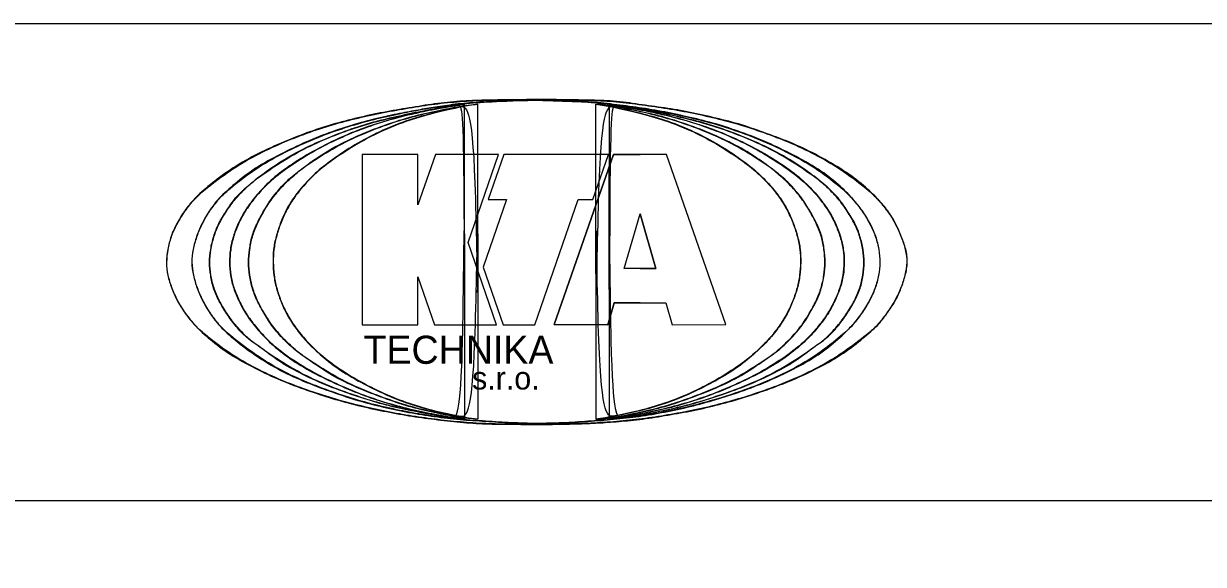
# Model space of a CAD drawing. Extents: x -729968 to -728918, y -1073811 to -1072326.
# Drawn here: x -729327.8 to -729080.2, y -1073214.6 to -1073101.1 of the extents above; entities that cross this region are included whole.
import ezdxf

# ---------------------------------------------------------------- set-up
doc = ezdxf.new("R2010")
doc.units = 0
doc.layers.add('_popis', color=7, linetype='Continuous')
doc.layers.add('Rozpiska_pole_6', color=7, linetype='Continuous')

msp = doc.modelspace()

# ---------------------------------------------------------------- linework, layer by layer
at = {"layer": '_popis'}
for p, q in [((-729198.42, -1073141.01), (-729195.1, -1073152.49)), ((-729195.1, -1073152.49), (-729198.42, -1073152.49))]:
    msp.add_line(p, q, dxfattribs=at)
for points in [[(-729256.7, -1073128.58), (-729256.7, -1073164.29), (-729245.02, -1073164.29), (-729245.02, -1073154.22), (-729241.52, -1073164.29), (-729228.52, -1073164.29), (-729234.52, -1073147.06), (-729228.09, -1073128.58), (-729241.34, -1073128.58), (-729245.02, -1073139.17), (-729245.02, -1073128.58), (-729256.7, -1073128.58)], [(-729256.7, -1073128.58), (-729256.7, -1073164.29), (-729245.02, -1073164.29), (-729245.02, -1073154.22), (-729241.52, -1073164.29), (-729228.52, -1073164.29), (-729234.52, -1073147.06), (-729228.09, -1073128.58), (-729241.34, -1073128.58), (-729245.02, -1073139.17), (-729245.02, -1073128.58), (-729256.7, -1073128.58)], [(-729227.02, -1073128.58), (-729230.3, -1073138.02), (-729226.42, -1073138.02), (-729231.36, -1073152.21), (-729227.16, -1073164.29), (-729220.51, -1073164.29), (-729211.37, -1073138.02), (-729208.35, -1073138.02), (-729205.06, -1073128.58), (-729227.02, -1073128.58)], [(-729227.02, -1073128.58), (-729230.3, -1073138.02), (-729226.42, -1073138.02), (-729231.36, -1073152.21), (-729227.16, -1073164.29), (-729220.51, -1073164.29), (-729211.37, -1073138.02), (-729208.35, -1073138.02), (-729205.06, -1073128.58), (-729227.02, -1073128.58)], [(-729198.42, -1073159.72), (-729203.83, -1073159.72), (-729205.15, -1073164.29), (-729216.42, -1073164.28), (-729203.99, -1073128.58), (-729198.42, -1073128.58)], [(-729198.42, -1073128.58), (-729203.99, -1073128.58), (-729216.42, -1073164.28), (-729205.15, -1073164.29), (-729203.83, -1073159.72), (-729198.42, -1073159.72)], [(-729198.42, -1073159.72), (-729193.01, -1073159.72), (-729191.69, -1073164.29), (-729180.43, -1073164.28), (-729192.85, -1073128.58), (-729198.42, -1073128.58)], [(-729198.42, -1073159.72), (-729193.01, -1073159.72), (-729191.69, -1073164.29), (-729180.43, -1073164.28), (-729192.85, -1073128.58), (-729198.42, -1073128.58)], [(-729198.42, -1073152.49), (-729201.74, -1073152.49), (-729198.42, -1073141.01)], [(-729198.42, -1073152.49), (-729201.74, -1073152.49), (-729198.42, -1073141.01)], [(-729198.42, -1073152.49), (-729195.1, -1073152.49), (-729198.42, -1073141.01)]]:
    msp.add_lwpolyline(points, dxfattribs=at)
for points in [[(-729220.07, -1073117.05), (-729222.09, -1073117.09), (-729225.67, -1073117.14), (-729231.03, -1073117.18), (-729236.17, -1073117.36), (-729241.53, -1073117.93), (-729246.88, -1073118.83), (-729252.26, -1073119.71), (-729257.63, -1073120.87), (-729263.01, -1073122.26), (-729268.39, -1073124.01), (-729273.74, -1073126.17), (-729279.19, -1073128.61), (-729284.59, -1073131.83), (-729288.82, -1073134.98), (-729292.04, -1073137.91), (-729294.02, -1073140.37), (-729295.67, -1073143.1), (-729296.94, -1073145.77), (-729297.53, -1073148.51), (-729297.93, -1073151.2), (-729297.6, -1073153.94), (-729296.75, -1073156.62), (-729295.56, -1073159.36), (-729293.8, -1073162.03), (-729291.93, -1073164.48), (-729288.75, -1073167.34), (-729284.65, -1073170.51), (-729279.15, -1073173.5), (-729273.79, -1073176.04), (-729268.37, -1073178.03), (-729263, -1073179.79), (-729257.64, -1073181.26), (-729252.28, -1073182.42), (-729246.92, -1073183.41), (-729241.53, -1073184.16), (-729236.17, -1073184.75), (-729230.8, -1073185.17), (-729225.44, -1073185.11), (-729220.07, -1073185.3), (-729214.71, -1073185.13), (-729210.61, -1073185.08), (-729208.3, -1073184.96), (-729207.78, -1073184.93)], [(-729220.07, -1073117.05), (-729226.13, -1073117.14), (-729230.79, -1073117.2), (-729236.15, -1073117.42), (-729241.51, -1073117.98), (-729246.87, -1073118.82), (-729252.24, -1073119.75), (-729257.6, -1073120.9), (-729262.96, -1073122.31), (-729268.33, -1073124.06), (-729273.69, -1073126.19), (-729279.02, -1073128.66), (-729284.39, -1073131.83), (-729289.75, -1073135.87), (-729291.84, -1073137.82), (-729294.02, -1073140.51), (-729295.65, -1073143.17), (-729296.86, -1073145.86), (-729297.5, -1073148.53), (-729297.81, -1073151.22), (-729297.53, -1073153.86), (-729296.72, -1073156.57), (-729295.51, -1073159.26), (-729293.83, -1073161.92), (-729291.67, -1073164.62), (-729289.76, -1073166.4), (-729284.4, -1073170.47), (-729279.04, -1073173.5), (-729273.74, -1073175.97), (-729268.32, -1073178.01), (-729262.94, -1073179.76), (-729257.61, -1073181.22), (-729252.28, -1073182.39), (-729246.89, -1073183.38), (-729241.52, -1073184.14), (-729236.13, -1073184.73), (-729230.83, -1073185.09), (-729225.43, -1073185.15), (-729220.07, -1073185.24), (-729214.71, -1073185.15), (-729209.34, -1073185.01), (-729203.98, -1073184.67), (-729198.65, -1073184.17), (-729193.27, -1073183.35), (-729187.91, -1073182.4), (-729182.55, -1073181.2), (-729177.18, -1073179.71), (-729171.82, -1073177.94), (-729166.46, -1073175.87), (-729161.13, -1073173.37), (-729155.73, -1073170.21), (-729150.34, -1073166.03), (-729148.74, -1073164.6), (-729146.64, -1073161.94), (-729144.87, -1073159.28), (-729143.63, -1073156.57), (-729142.76, -1073153.91), (-729142.33, -1073151.22), (-729142.65, -1073148.55), (-729143.57, -1073145.85), (-729144.78, -1073143.12), (-729146.38, -1073140.51), (-729148.65, -1073137.82), (-729150.3, -1073136.19), (-729155.72, -1073132), (-729161.08, -1073128.83), (-729166.4, -1073126.29), (-729171.79, -1073124.22), (-729177.18, -1073122.37), (-729182.51, -1073120.96), (-729187.91, -1073119.76), (-729193.3, -1073118.83), (-729198.68, -1073118.07), (-729204, -1073117.4), (-729209.35, -1073117.2), (-729214.7, -1073117.11), (-729220.07, -1073117.05), (-729220.07, -1073117.05), (-729220.07, -1073117.05)], [(-729207.78, -1073184.93), (-729206.52, -1073184.86), (-729203.47, -1073184.64), (-729198.61, -1073184.24), (-729193.27, -1073183.36), (-729187.89, -1073182.45), (-729182.52, -1073181.23), (-729177.14, -1073179.75), (-729171.77, -1073177.97), (-729166.39, -1073175.91), (-729160.98, -1073173.39), (-729155.47, -1073170.26), (-729151.54, -1073167.04), (-729148.37, -1073164.39), (-729146.68, -1073161.99), (-729144.81, -1073159.4), (-729143.61, -1073156.64), (-729142.7, -1073153.95), (-729142.19, -1073151.24), (-729142.55, -1073148.46), (-729143.58, -1073145.8), (-729144.72, -1073143.06), (-729146.4, -1073140.33), (-729148.35, -1073138.08), (-729151.36, -1073135.11), (-729155.48, -1073132), (-729160.95, -1073128.81), (-729166.33, -1073126.22), (-729171.76, -1073124.22), (-729177.09, -1073122.29), (-729182.51, -1073120.95), (-729187.88, -1073119.7), (-729193.29, -1073118.8), (-729198.66, -1073118.1), (-729203.99, -1073117.27), (-729209.35, -1073117.21), (-729214.71, -1073117.09), (-729218.28, -1073117.07), (-729220.07, -1073117.05)], [(-729220.07, -1073117.2), (-729218.28, -1073117.27), (-729214.7, -1073117.42), (-729209.33, -1073117.47), (-729203.98, -1073118.06), (-729198.62, -1073118.74), (-729193.24, -1073119.63), (-729187.89, -1073120.82), (-729182.48, -1073122.1), (-729177.13, -1073123.92), (-729171.72, -1073125.99), (-729166.38, -1073128.63), (-729160.8, -1073131.63), (-729156.69, -1073134.91), (-729153.64, -1073137.96), (-729151.72, -1073140.39), (-729150.07, -1073143.1), (-729148.84, -1073145.79), (-729148.2, -1073148.52), (-729147.97, -1073151.23), (-729148.17, -1073153.96), (-729148.99, -1073156.65), (-729150.19, -1073159.35), (-729151.9, -1073162.03), (-729153.72, -1073164.42), (-729156.81, -1073167.32), (-729160.8, -1073170.61), (-729166.34, -1073173.73), (-729171.75, -1073176.24), (-729177.13, -1073178.32), (-729182.52, -1073180.01), (-729187.88, -1073181.51), (-729193.26, -1073182.62), (-729198.62, -1073183.6), (-729203.99, -1073184.13), (-729209.35, -1073184.58), (-729214.7, -1073184.93), (-729220.07, -1073185.1), (-729225.44, -1073184.9), (-729230.8, -1073184.52), (-729236.17, -1073184.23), (-729241.54, -1073183.59), (-729246.91, -1073182.72), (-729252.27, -1073181.58), (-729257.67, -1073180.25), (-729263, -1073178.41), (-729268.42, -1073176.47), (-729273.85, -1073174), (-729279.24, -1073170.74), (-729283.47, -1073167.52), (-729286.7, -1073164.57), (-729288.63, -1073162.06), (-729290.23, -1073159.33), (-729291.43, -1073156.64), (-729292.18, -1073153.94), (-729292.65, -1073151.22), (-729292.24, -1073148.5), (-729291.54, -1073145.79), (-729290.41, -1073143.09), (-729288.82, -1073140.39), (-729286.89, -1073137.76), (-729283.54, -1073134.78), (-729279.31, -1073131.41), (-729273.76, -1073128.45), (-729268.42, -1073125.86), (-729263.03, -1073123.76), (-729257.65, -1073122.04), (-729252.27, -1073120.67), (-729247.69, -1073119.76), (-729244.11, -1073119.1), (-729240.54, -1073118.53), (-729236.17, -1073117.89), (-729230.8, -1073117.55), (-729225.43, -1073117.33), (-729221.86, -1073117.24), (-729220.07, -1073117.2)], [(-729220.07, -1073117.2), (-729225.43, -1073117.34), (-729230.79, -1073117.57), (-729236.15, -1073117.96), (-729241.51, -1073118.69), (-729243.92, -1073119.08), (-729246.87, -1073119.61), (-729252.24, -1073120.71), (-729257.6, -1073122.09), (-729262.97, -1073123.8), (-729268.33, -1073125.91), (-729273.7, -1073128.46), (-729279.03, -1073131.46), (-729284.39, -1073135.56), (-729286.78, -1073137.81), (-729288.83, -1073140.5), (-729290.37, -1073143.17), (-729291.49, -1073145.87), (-729292.2, -1073148.53), (-729292.5, -1073151.22), (-729292.14, -1073153.9), (-729291.38, -1073156.56), (-729290.2, -1073159.25), (-729288.63, -1073161.94), (-729286.52, -1073164.63), (-729284.39, -1073166.65), (-729279.03, -1073170.74), (-729273.7, -1073173.95), (-729268.34, -1073176.41), (-729262.98, -1073178.41), (-729257.61, -1073180.18), (-729252.25, -1073181.56), (-729246.89, -1073182.68), (-729241.52, -1073183.55), (-729236.16, -1073184.17), (-729230.8, -1073184.53), (-729225.43, -1073184.87), (-729220.07, -1073185.04), (-729214.71, -1073184.9), (-729209.34, -1073184.56), (-729204.01, -1073184.12), (-729198.65, -1073183.53), (-729193.27, -1073182.6), (-729187.92, -1073181.45), (-729182.56, -1073179.99), (-729177.18, -1073178.28), (-729171.82, -1073176.2), (-729166.46, -1073173.71), (-729161.09, -1073170.57), (-729155.73, -1073166.29), (-729154.02, -1073164.62), (-729151.89, -1073161.93), (-729150.23, -1073159.26), (-729149.02, -1073156.57), (-729148.27, -1073153.91), (-729148.04, -1073151.24), (-729148.27, -1073148.54), (-729148.91, -1073145.88), (-729150.09, -1073143.19), (-729151.72, -1073140.5), (-729153.85, -1073137.81), (-729155.73, -1073135.91), (-729161.09, -1073131.67), (-729166.46, -1073128.63), (-729171.82, -1073126.05), (-729177.18, -1073123.95), (-729182.55, -1073122.17), (-729187.9, -1073120.83), (-729193.26, -1073119.68), (-729198.64, -1073118.77), (-729203.99, -1073118.07), (-729209.34, -1073117.56), (-729214.7, -1073117.39), (-729220.07, -1073117.2), (-729220.07, -1073117.2), (-729220.07, -1073117.2)], [(-729235.26, -1073184.04), (-729236.28, -1073183.96), (-729238.39, -1073183.79), (-729242.28, -1073183.19), (-729246.92, -1073182.23), (-729252.35, -1073181.08), (-729257.69, -1073179.37), (-729263.08, -1073177.51), (-729268.47, -1073175.18), (-729273.95, -1073172.24), (-729277.75, -1073169.24), (-729281.14, -1073167.01), (-729283.15, -1073164.75), (-729285.19, -1073162.02), (-729286.78, -1073159.33), (-729288.02, -1073156.67), (-729288.56, -1073153.92), (-729288.86, -1073151.22), (-729288.57, -1073148.51), (-729287.95, -1073145.8), (-729286.91, -1073143.04), (-729285.24, -1073140.43), (-729283.33, -1073137.59), (-729281.13, -1073135.48), (-729277.93, -1073132.87), (-729273.9, -1073130.04), (-729268.46, -1073126.98), (-729263.03, -1073124.71), (-729257.69, -1073122.67), (-729252.28, -1073121.22), (-729246.87, -1073120), (-729241.52, -1073118.94), (-729237.65, -1073118.25), (-729235.56, -1073118.12), (-729235.28, -1073118.1)], [(-729235.26, -1073184.04), (-729238.33, -1073183.75), (-729241.54, -1073183.28), (-729246.9, -1073182.23), (-729252.29, -1073181), (-729257.67, -1073179.35), (-729263, -1073177.46), (-729268.34, -1073175.15), (-729273.72, -1073172.17), (-729279.11, -1073168.36), (-729280.55, -1073167.33), (-729283.18, -1073164.63), (-729285.21, -1073161.88), (-729286.76, -1073159.26), (-729287.92, -1073156.6), (-729288.53, -1073153.88), (-729288.77, -1073151.2), (-729288.53, -1073148.58), (-729287.9, -1073145.85), (-729286.85, -1073143.15), (-729285.27, -1073140.49), (-729283.35, -1073137.81), (-729280.62, -1073135.08), (-729279.14, -1073133.87), (-729273.72, -1073130.05), (-729268.3, -1073127.03), (-729262.96, -1073124.71), (-729257.68, -1073122.77), (-729252.19, -1073121.24), (-729246.88, -1073120.03), (-729241.49, -1073118.95), (-729236.12, -1073118.16), (-729235.28, -1073118.1), (-729235.26, -1073184.04), (-729235.28, -1073118.1)], [(-729235.28, -1073118.1), (-729237.21, -1073118.39), (-729241.1, -1073118.98), (-729246.77, -1073120.14), (-729252.3, -1073121.67), (-729257.71, -1073123.45), (-729263.06, -1073125.82), (-729268.47, -1073128.65), (-729273.21, -1073131.75), (-729276.94, -1073134.86), (-729279.41, -1073137.71), (-729281.36, -1073140.38), (-729282.8, -1073143.08), (-729283.84, -1073145.8), (-729284.46, -1073148.52), (-729284.64, -1073151.23), (-729284.44, -1073153.94), (-729283.76, -1073156.65), (-729282.61, -1073159.31), (-729281.2, -1073162.07), (-729279.18, -1073164.71), (-729276.73, -1073167.5), (-729273.14, -1073170.6), (-729268.47, -1073173.64), (-729263.04, -1073176.37), (-729257.65, -1073178.66), (-729252.3, -1073180.58), (-729246.91, -1073182.01), (-729242.05, -1073183), (-729238.17, -1073183.65), (-729236.07, -1073183.93), (-729235.26, -1073184.04)], [(-729235.28, -1073118.1), (-729241.06, -1073119.02), (-729246.87, -1073120.23), (-729252.26, -1073121.7), (-729257.64, -1073123.53), (-729262.95, -1073125.84), (-729268.31, -1073128.67), (-729273.69, -1073132.24), (-729277.05, -1073135.13), (-729279.45, -1073137.83), (-729281.34, -1073140.49), (-729282.76, -1073143.14), (-729283.79, -1073145.86), (-729284.39, -1073148.56), (-729284.58, -1073151.22), (-729284.37, -1073153.92), (-729283.71, -1073156.57), (-729282.6, -1073159.25), (-729281.16, -1073161.96), (-729279.21, -1073164.61), (-729276.82, -1073167.28), (-729273.64, -1073170.07), (-729268.33, -1073173.59), (-729262.94, -1073176.35), (-729257.59, -1073178.63), (-729252.23, -1073180.52), (-729246.89, -1073181.96), (-729241.51, -1073183.07), (-729237.7, -1073183.7), (-729235.26, -1073184.04), (-729235.28, -1073118.1), (-729235.26, -1073184.04)], [(-729232.46, -1073184.13), (-729233.7, -1073184.02), (-729236.75, -1073183.76), (-729241.53, -1073182.73), (-729246.94, -1073181.52), (-729252.28, -1073179.67), (-729257.69, -1073177.59), (-729263.18, -1073174.99), (-729267.22, -1073172.12), (-729270.8, -1073169.76), (-729273.17, -1073167.41), (-729275.61, -1073164.79), (-729277.26, -1073161.97), (-729278.8, -1073159.35), (-729279.84, -1073156.65), (-729280.41, -1073153.94), (-729280.7, -1073151.23), (-729280.38, -1073148.53), (-729279.96, -1073145.79), (-729278.85, -1073143.11), (-729277.42, -1073140.44), (-729275.68, -1073137.69), (-729273.41, -1073134.94), (-729270.84, -1073132.66), (-729267.35, -1073130.03), (-729263.13, -1073127.27), (-729257.7, -1073124.6), (-729252.31, -1073122.51), (-729246.95, -1073120.74), (-729241.55, -1073119.52), (-729236.74, -1073118.52), (-729233.69, -1073118.17), (-729232.46, -1073118.03)], [(-729232.46, -1073184.13), (-729236.15, -1073183.75), (-729241.54, -1073182.72), (-729246.85, -1073181.44), (-729252.24, -1073179.65), (-729257.61, -1073177.54), (-729262.95, -1073174.91), (-729268.32, -1073171.4), (-729270.34, -1073169.99), (-729273.26, -1073167.28), (-729275.58, -1073164.63), (-729277.29, -1073161.93), (-729278.76, -1073159.25), (-729279.78, -1073156.57), (-729280.36, -1073153.95), (-729280.6, -1073151.23), (-729280.36, -1073148.52), (-729279.86, -1073145.87), (-729278.84, -1073143.21), (-729277.39, -1073140.47), (-729275.68, -1073137.82), (-729273.45, -1073135.13), (-729270.51, -1073132.45), (-729268.3, -1073130.77), (-729262.95, -1073127.31), (-729257.62, -1073124.66), (-729252.23, -1073122.53), (-729246.91, -1073120.82), (-729241.54, -1073119.53), (-729236.15, -1073118.5), (-729232.46, -1073118.03), (-729232.46, -1073184.13), (-729232.46, -1073118.03)], [(-729232.46, -1073118.03), (-729233.69, -1073118.21), (-729236.74, -1073118.65), (-729241.54, -1073119.84), (-729246.97, -1073121.28), (-729252.37, -1073123.39), (-729257.76, -1073126.16), (-729262.49, -1073129.25), (-729266.36, -1073132.23), (-729269.06, -1073135.02), (-729271.19, -1073137.7), (-729272.81, -1073140.41), (-729273.97, -1073143.13), (-729274.84, -1073145.82), (-729275.4, -1073148.51), (-729275.48, -1073151.22), (-729275.32, -1073153.92), (-729274.8, -1073156.63), (-729273.84, -1073159.3), (-729272.66, -1073162.03), (-729270.97, -1073164.7), (-729268.84, -1073167.42), (-729266.14, -1073170.08), (-729262.46, -1073173.14), (-729257.77, -1073176.07), (-729252.35, -1073178.74), (-729246.98, -1073180.94), (-729241.56, -1073182.44), (-729236.72, -1073183.45), (-729233.7, -1073183.93), (-729232.46, -1073184.13)], [(-729232.46, -1073118.03), (-729236.15, -1073118.62), (-729241.5, -1073119.85), (-729246.89, -1073121.37), (-729252.24, -1073123.44), (-729257.61, -1073126.2), (-729262.96, -1073129.68), (-729266.48, -1073132.48), (-729269.09, -1073135.14), (-729271.19, -1073137.83), (-729272.77, -1073140.49), (-729273.94, -1073143.18), (-729274.8, -1073145.86), (-729275.32, -1073148.55), (-729275.44, -1073151.21), (-729275.27, -1073153.9), (-729274.74, -1073156.59), (-729273.83, -1073159.25), (-729272.63, -1073161.93), (-729270.96, -1073164.62), (-729268.88, -1073167.25), (-729266.19, -1073169.95), (-729262.97, -1073172.62), (-729257.62, -1073176.04), (-729252.25, -1073178.71), (-729246.9, -1073180.85), (-729241.49, -1073182.4), (-729236.15, -1073183.51), (-729232.46, -1073184.13), (-729232.46, -1073118.03), (-729232.46, -1073184.13)], [(-729207.68, -1073184.13), (-729206.45, -1073184.02), (-729203.39, -1073183.76), (-729198.61, -1073182.73), (-729193.2, -1073181.52), (-729187.86, -1073179.67), (-729182.45, -1073177.59), (-729176.97, -1073174.99), (-729172.93, -1073172.12), (-729169.34, -1073169.76), (-729166.97, -1073167.41), (-729164.54, -1073164.79), (-729162.88, -1073161.97), (-729161.34, -1073159.35), (-729160.31, -1073156.65), (-729159.74, -1073153.94), (-729159.44, -1073151.23), (-729159.76, -1073148.53), (-729160.19, -1073145.79), (-729161.29, -1073143.11), (-729162.73, -1073140.44), (-729164.47, -1073137.69), (-729166.74, -1073134.94), (-729169.3, -1073132.66), (-729172.79, -1073130.03), (-729177.01, -1073127.27), (-729182.44, -1073124.6), (-729187.83, -1073122.51), (-729193.19, -1073120.74), (-729198.59, -1073119.52), (-729203.4, -1073118.52), (-729206.45, -1073118.17), (-729207.68, -1073118.03)], [(-729207.68, -1073118.03), (-729206.45, -1073118.21), (-729203.4, -1073118.65), (-729198.6, -1073119.84), (-729193.18, -1073121.28), (-729187.77, -1073123.39), (-729182.38, -1073126.16), (-729177.65, -1073129.25), (-729173.79, -1073132.23), (-729171.08, -1073135.02), (-729168.95, -1073137.7), (-729167.34, -1073140.41), (-729166.17, -1073143.13), (-729165.31, -1073145.82), (-729164.74, -1073148.51), (-729164.66, -1073151.22), (-729164.82, -1073153.92), (-729165.34, -1073156.63), (-729166.3, -1073159.3), (-729167.48, -1073162.03), (-729169.17, -1073164.7), (-729171.31, -1073167.42), (-729174.01, -1073170.08), (-729177.69, -1073173.14), (-729182.38, -1073176.07), (-729187.79, -1073178.74), (-729193.17, -1073180.94), (-729198.59, -1073182.44), (-729203.42, -1073183.45), (-729206.45, -1073183.93), (-729207.68, -1073184.13)], [(-729207.68, -1073118.03), (-729203.99, -1073118.62), (-729198.64, -1073119.85), (-729193.26, -1073121.37), (-729187.9, -1073123.44), (-729182.54, -1073126.2), (-729177.18, -1073129.68), (-729173.66, -1073132.48), (-729171.06, -1073135.14), (-729168.95, -1073137.83), (-729167.37, -1073140.49), (-729166.2, -1073143.18), (-729165.35, -1073145.86), (-729164.82, -1073148.55), (-729164.7, -1073151.21), (-729164.88, -1073153.9), (-729165.4, -1073156.59), (-729166.31, -1073159.25), (-729167.51, -1073161.93), (-729169.18, -1073164.62), (-729171.26, -1073167.25), (-729173.96, -1073169.95), (-729177.17, -1073172.62), (-729182.53, -1073176.04), (-729187.89, -1073178.71), (-729193.24, -1073180.85), (-729198.66, -1073182.4), (-729203.99, -1073183.51), (-729207.68, -1073184.13), (-729207.68, -1073118.03), (-729207.68, -1073184.13)], [(-729207.68, -1073184.13), (-729203.99, -1073183.75), (-729198.61, -1073182.72), (-729193.3, -1073181.44), (-729187.91, -1073179.65), (-729182.53, -1073177.54), (-729177.2, -1073174.91), (-729171.82, -1073171.4), (-729169.8, -1073169.99), (-729166.88, -1073167.28), (-729164.57, -1073164.63), (-729162.86, -1073161.93), (-729161.39, -1073159.25), (-729160.36, -1073156.57), (-729159.78, -1073153.95), (-729159.54, -1073151.23), (-729159.78, -1073148.52), (-729160.28, -1073145.87), (-729161.3, -1073143.21), (-729162.75, -1073140.47), (-729164.46, -1073137.82), (-729166.69, -1073135.13), (-729169.64, -1073132.45), (-729171.85, -1073130.77), (-729177.19, -1073127.31), (-729182.52, -1073124.66), (-729187.91, -1073122.53), (-729193.24, -1073120.82), (-729198.6, -1073119.53), (-729204, -1073118.5), (-729207.68, -1073118.03), (-729207.68, -1073184.13), (-729207.68, -1073118.03)], [(-729204.86, -1073118.1), (-729202.93, -1073118.39), (-729199.05, -1073118.98), (-729193.37, -1073120.14), (-729187.84, -1073121.67), (-729182.43, -1073123.45), (-729177.08, -1073125.82), (-729171.67, -1073128.65), (-729166.93, -1073131.75), (-729163.21, -1073134.86), (-729160.73, -1073137.71), (-729158.79, -1073140.38), (-729157.34, -1073143.08), (-729156.3, -1073145.8), (-729155.69, -1073148.52), (-729155.5, -1073151.23), (-729155.7, -1073153.94), (-729156.38, -1073156.65), (-729157.53, -1073159.31), (-729158.94, -1073162.07), (-729160.96, -1073164.71), (-729163.41, -1073167.5), (-729167, -1073170.6), (-729171.67, -1073173.64), (-729177.11, -1073176.37), (-729182.49, -1073178.66), (-729187.84, -1073180.58), (-729193.23, -1073182.01), (-729198.09, -1073183), (-729201.98, -1073183.65), (-729204.07, -1073183.93), (-729204.88, -1073184.04)], [(-729204.88, -1073184.04), (-729203.86, -1073183.96), (-729201.75, -1073183.79), (-729197.87, -1073183.19), (-729193.22, -1073182.23), (-729187.8, -1073181.08), (-729182.46, -1073179.37), (-729177.07, -1073177.51), (-729171.67, -1073175.18), (-729166.2, -1073172.24), (-729162.39, -1073169.24), (-729159, -1073167.01), (-729156.99, -1073164.75), (-729154.95, -1073162.02), (-729153.36, -1073159.33), (-729152.13, -1073156.67), (-729151.58, -1073153.92), (-729151.28, -1073151.22), (-729151.57, -1073148.51), (-729152.19, -1073145.8), (-729153.23, -1073143.04), (-729154.9, -1073140.43), (-729156.82, -1073137.59), (-729159.01, -1073135.48), (-729162.21, -1073132.87), (-729166.25, -1073130.04), (-729171.68, -1073126.98), (-729177.11, -1073124.71), (-729182.46, -1073122.67), (-729187.86, -1073121.22), (-729193.27, -1073120), (-729198.62, -1073118.94), (-729202.5, -1073118.25), (-729204.58, -1073118.12), (-729204.86, -1073118.1)], [(-729204.88, -1073184.04), (-729201.81, -1073183.75), (-729198.6, -1073183.28), (-729193.24, -1073182.23), (-729187.85, -1073181), (-729182.48, -1073179.35), (-729177.14, -1073177.46), (-729171.8, -1073175.15), (-729166.43, -1073172.17), (-729161.04, -1073168.36), (-729159.59, -1073167.33), (-729156.96, -1073164.63), (-729154.93, -1073161.88), (-729153.38, -1073159.26), (-729152.22, -1073156.6), (-729151.61, -1073153.88), (-729151.38, -1073151.2), (-729151.61, -1073148.58), (-729152.24, -1073145.85), (-729153.3, -1073143.15), (-729154.87, -1073140.49), (-729156.79, -1073137.81), (-729159.53, -1073135.08), (-729161, -1073133.87), (-729166.43, -1073130.05), (-729171.84, -1073127.03), (-729177.18, -1073124.71), (-729182.47, -1073122.77), (-729187.95, -1073121.24), (-729193.26, -1073120.03), (-729198.65, -1073118.95), (-729204.02, -1073118.16), (-729204.86, -1073118.1), (-729204.88, -1073184.04), (-729204.86, -1073118.1)], [(-729204.86, -1073118.1), (-729199.08, -1073119.02), (-729193.27, -1073120.23), (-729187.88, -1073121.7), (-729182.5, -1073123.53), (-729177.19, -1073125.84), (-729171.83, -1073128.67), (-729166.45, -1073132.24), (-729163.09, -1073135.13), (-729160.7, -1073137.83), (-729158.8, -1073140.49), (-729157.38, -1073143.14), (-729156.36, -1073145.86), (-729155.75, -1073148.56), (-729155.57, -1073151.22), (-729155.78, -1073153.92), (-729156.43, -1073156.57), (-729157.54, -1073159.25), (-729158.98, -1073161.96), (-729160.93, -1073164.61), (-729163.33, -1073167.28), (-729166.51, -1073170.07), (-729171.82, -1073173.59), (-729177.2, -1073176.35), (-729182.56, -1073178.63), (-729187.92, -1073180.52), (-729193.25, -1073181.96), (-729198.63, -1073183.07), (-729202.44, -1073183.7), (-729204.88, -1073184.04), (-729204.86, -1073118.1), (-729204.88, -1073184.04)]]:
    msp.add_open_spline(points, degree=3, dxfattribs=at)
at = {"layer": 'Rozpiska_pole_6'}
msp.add_line((-729868.27, -1073201.15), (-729018.27, -1073201.15), dxfattribs=at)
msp.add_lwpolyline([(-729868.27, -1073101.15), (-729018.27, -1073101.15), (-729018.27, -1073351.15), (-729868.27, -1073351.15)], close=True, dxfattribs=at)

# ---------------------------------------------------------------- texts
at = {"layer": '_popis'}
for s, height, p in [('TECHNIKA', 5.898, (-729256.46, -1073172.49)), ('s.r.o.', 4.772, (-729233.67, -1073177.88))]:
    msp.add_text(s, height=height, dxfattribs=at).set_placement(p)

doc.saveas('drawing.dxf')
